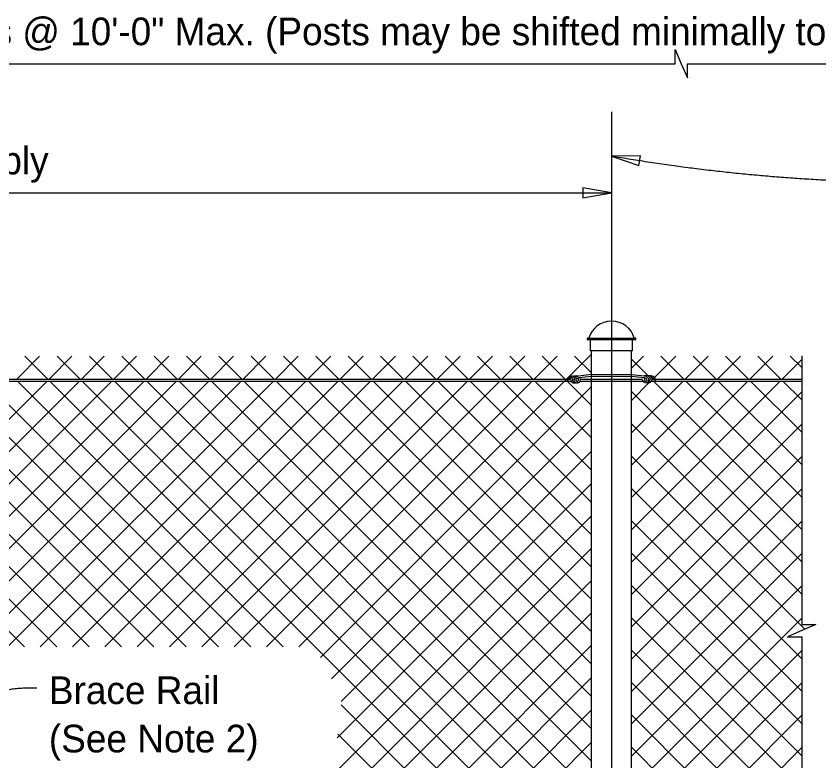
# Model space of a CAD drawing. Extents: x 0.2 to 40.8, y 0.5 to 25.7.
# Drawn here: x 10.28 to 16.13, y 20.28 to 25.7 of the extents above; entities that cross this region are included whole.
import ezdxf

# ---------------------------------------------------------------- set-up
doc = ezdxf.new("R2010")
doc.units = 0
for name, color, linetype in [('CL_Major', 7, 'Continuous'), ('Dimension', 7, 'Continuous'), ('Miscellaneous', 7, 'Continuous'), ('SteelMisc', 7, 'Continuous'), ('SteelMisc_h', 7, 'Continuous'), ('TextStructures', 7, 'Continuous')]:
    doc.layers.add(name, color=color, linetype=linetype)

msp = doc.modelspace()

# ---------------------------------------------------------------- linework, layer by layer
at = {"layer": 'CL_Major'}
msp.add_line((14.615, 25.0052), (14.615, 14.7584), dxfattribs=at)
at = {"layer": 'Dimension'}
for p, q in [((0.2352, 25.3556), (13.615, 25.3556)), ((4.615, 24.4146), (14.615, 24.4146))]:
    msp.add_line(p, q, dxfattribs=at)
for points in [[(13.615, 25.3556), (15.0787, 25.3556), (15.0787, 25.4589), (15.1237, 25.3556), (15.1687, 25.2523), (15.1687, 25.3556), (28.4596, 25.3556)], [(16.002, 23.2265), (16.002, 21.2702), (16.1053, 21.2702), (16.002, 21.2252), (15.8987, 21.1802), (16.002, 21.1802), (16.002, 20.2867)], [(16.002, 20.2867), (16.002, 19.2689), (16.1053, 19.2689), (16.002, 19.2239), (15.8987, 19.1789), (16.002, 19.1789), (16.002, 16.9746)]]:
    msp.add_lwpolyline(points, dxfattribs=at)
for points in [[(14.615, 24.6814), (14.815, 24.6135), (14.8262, 24.6832)], [(14.615, 24.4146), (14.4068, 24.4499), (14.4068, 24.3793)]]:
    msp.add_lwpolyline(points, close=True, dxfattribs=at)
for points in [[(18.5966, 24.4827), (17.7933, 24.4827), (16.4039, 24.4827), (15.2225, 24.5773), (14.615, 24.6814)], [(10.4281, 20.8052), (10.1586, 20.8133), (10.0405, 20.6549), (10.0376, 20.5337), (10.0422, 20.3659), (10.0503, 19.9529)]]:
    msp.add_open_spline(points, degree=2, dxfattribs=at)
at = {"layer": 'Miscellaneous'}
for p, q in [((12.336, 21.1064), (14.4692, 23.2396)), ((10.2805, 23.0578), (10.4472, 23.2245)), ((10.3397, 23.2245), (10.5064, 23.0578)), ((10.5162, 23.0578), (10.6829, 23.2245)), ((10.5754, 23.2245), (10.7421, 23.0578)), ((10.7519, 23.0578), (10.9186, 23.2245)), ((10.8111, 23.2245), (10.9778, 23.0578)), ((10.9876, 23.0578), (11.1543, 23.2245)), ((11.0468, 23.2245), (11.2135, 23.0578)), ((11.2233, 23.0578), (11.39, 23.2245)), ((11.2825, 23.2245), (11.4492, 23.0578)), ((11.459, 23.0578), (11.6257, 23.2245)), ((11.5182, 23.2245), (11.6849, 23.0578)), ((11.6947, 23.0578), (11.8614, 23.2245)), ((11.7539, 23.2245), (11.9206, 23.0578)), ((11.9304, 23.0578), (12.0971, 23.2245)), ((11.9896, 23.2245), (12.1563, 23.0578)), ((12.1661, 23.0578), (12.3328, 23.2245)), ((12.2253, 23.2245), (12.392, 23.0578)), ((12.4018, 23.0578), (12.5685, 23.2245)), ((12.461, 23.2245), (12.6277, 23.0578)), ((12.6375, 23.0578), (12.8042, 23.2245)), ((12.6967, 23.2245), (12.8634, 23.0578)), ((12.8732, 23.0578), (13.0399, 23.2245)), ((12.9324, 23.2245), (13.0991, 23.0578)), ((13.1089, 23.0578), (13.2756, 23.2245)), ((13.1681, 23.2245), (13.3348, 23.0578)), ((13.3446, 23.0578), (13.5113, 23.2245)), ((13.4038, 23.2245), (13.5705, 23.0578)), ((13.5803, 23.0578), (13.747, 23.2245)), ((13.6396, 23.2245), (13.8062, 23.0578)), ((13.816, 23.0578), (13.9827, 23.2245)), ((13.8753, 23.2245), (14.0419, 23.0578)), ((14.0517, 23.0578), (14.2184, 23.2245)), ((14.111, 23.2245), (14.2776, 23.0578)), ((14.2874, 23.0578), (14.4541, 23.2245)), ((14.3467, 23.2245), (14.4692, 23.1019)), ((14.7609, 23.1379), (14.8475, 23.2245)), ((14.7609, 23.2036), (14.8832, 23.0814)), ((14.928, 23.0694), (15.0832, 23.2245)), ((14.9757, 23.2245), (15.1424, 23.0578)), ((15.1522, 23.0578), (15.3189, 23.2245)), ((15.2114, 23.2245), (15.3781, 23.0578)), ((15.3879, 23.0578), (15.5546, 23.2245)), ((15.4471, 23.2245), (15.6138, 23.0578)), ((15.6236, 23.0578), (15.7903, 23.2245)), ((15.6828, 23.2245), (15.8495, 23.0578)), ((15.8593, 23.0578), (16.002, 23.2005)), ((15.9185, 23.2245), (16.002, 23.1411)), ((14.9165, 23.0578), (14.921, 23.0623)), ((8.3383, 20.88), (10.5014, 23.0431)), ((8.3998, 23.0431), (10.3365, 21.1064)), ((8.4925, 20.7985), (10.7372, 23.0431)), ((8.6355, 23.0431), (10.5722, 21.1064)), ((8.6467, 20.717), (10.9729, 23.0431)), ((8.8009, 20.6355), (11.2086, 23.0431)), ((8.8712, 23.0431), (10.8079, 21.1064)), ((8.9552, 20.554), (11.4443, 23.0431)), ((9.1069, 23.0431), (11.0436, 21.1064)), ((9.1094, 20.4725), (11.68, 23.0431)), ((9.2636, 20.391), (11.9157, 23.0431)), ((9.3426, 23.0431), (11.2793, 21.1064)), ((9.5783, 23.0431), (11.515, 21.1064)), ((9.814, 23.0431), (11.7507, 21.1064)), ((10.0497, 23.0431), (11.9864, 21.1064)), ((10.2043, 21.096), (12.1514, 23.0431)), ((10.2854, 23.0431), (12.2221, 21.1064)), ((10.4504, 21.1064), (12.3871, 23.0431)), ((10.5211, 23.0431), (14.4692, 19.095)), ((10.6861, 21.1064), (12.6228, 23.0431)), ((10.7568, 23.0431), (14.4692, 19.3307)), ((10.9218, 21.1064), (12.8585, 23.0431)), ((10.9925, 23.0431), (14.4692, 19.5664)), ((11.1575, 21.1064), (13.0942, 23.0431)), ((11.2282, 23.0431), (14.4692, 19.8021)), ((11.3932, 21.1064), (13.3299, 23.0431)), ((11.4639, 23.0431), (14.4692, 20.0378)), ((11.6289, 21.1064), (13.5656, 23.0431)), ((11.6996, 23.0431), (14.4692, 20.2735)), ((11.8646, 21.1064), (13.8013, 23.0431)), ((11.9353, 23.0431), (14.4692, 20.5092)), ((12.1003, 21.1064), (14.037, 23.0431)), ((12.1003, 21.1064), (14.037, 23.0431)), ((12.1711, 23.0431), (14.4692, 20.7449)), ((12.4068, 23.0431), (14.4692, 20.9806)), ((12.4951, 21.0298), (14.4692, 23.0039)), ((12.6425, 23.0431), (14.4692, 21.2163)), ((12.8782, 23.0431), (14.4692, 21.452)), ((13.1139, 23.0431), (14.4692, 21.6877)), ((13.3496, 23.0431), (14.4692, 21.9234)), ((13.5853, 23.0431), (14.4692, 22.1591)), ((13.821, 23.0431), (14.4692, 22.3948)), ((14.0567, 23.0431), (14.4692, 22.6305)), ((14.2924, 23.0431), (14.4692, 22.8662)), ((14.7609, 21.9594), (15.8446, 23.0431)), ((14.7609, 22.4308), (15.3732, 23.0431)), ((14.7609, 22.6665), (15.1375, 23.0431)), ((14.7609, 22.9022), (14.8904, 23.0317)), ((14.7653, 22.1995), (15.6089, 23.0431)), ((14.9214, 23.0431), (16.002, 21.9626)), ((15.1572, 23.0431), (16.002, 22.1983)), ((15.3929, 23.0431), (16.002, 22.434)), ((15.6286, 23.0431), (16.002, 22.6697)), ((15.8643, 23.0431), (16.002, 22.9054)), ((14.7609, 22.9679), (16.002, 21.7268)), ((14.7609, 21.7237), (16.002, 22.9648)), ((12.5756, 20.8746), (14.4692, 22.7682)), ((14.7609, 22.7322), (16.002, 21.4911)), ((14.7609, 21.488), (16.002, 22.7291)), ((12.6439, 20.7072), (14.4692, 22.5325)), ((14.7609, 22.4965), (16.023, 21.2344)), ((14.7609, 21.2523), (16.002, 22.4934)), ((12.6167, 20.4443), (14.4692, 22.2968)), ((14.7609, 22.2608), (16.002, 21.0197)), ((14.7609, 21.0166), (16.002, 22.2577)), ((11.5767, 19.1686), (14.4692, 22.0611)), ((14.7609, 22.0251), (16.002, 20.784)), ((14.7609, 20.7809), (16.002, 22.022)), ((11.7309, 19.0871), (14.4692, 21.8254)), ((14.7609, 21.7894), (16.002, 20.5483)), ((14.7609, 20.5452), (16.002, 21.7863)), ((11.8851, 19.0056), (14.4692, 21.5897)), ((14.7609, 21.5537), (16.002, 20.3126)), ((14.7609, 20.3095), (16.002, 21.5506)), ((12.0393, 18.9241), (14.4692, 21.354)), ((14.7609, 21.318), (16.002, 20.0769)), ((14.7609, 20.0738), (16.002, 21.3149)), ((12.1936, 18.8426), (14.4692, 21.1183)), ((14.7609, 21.0823), (16.002, 19.8412)), ((14.7609, 19.8381), (16.002, 21.0792)), ((12.3478, 18.7611), (14.4692, 20.8826)), ((14.7609, 20.8466), (16.002, 19.6055)), ((14.7609, 19.6024), (16.002, 20.8435)), ((12.6449, 20.6836), (14.4692, 18.8593)), ((12.502, 18.6796), (14.4692, 20.6469)), ((14.7609, 20.6109), (16.002, 19.3698)), ((14.7609, 19.3667), (16.002, 20.6078)), ((12.6214, 20.4714), (14.4692, 18.6236)), ((12.6562, 18.5982), (14.4692, 20.4112)), ((14.7609, 20.3752), (15.9395, 19.1966)), ((14.7609, 19.131), (16.002, 20.3721))]:
    msp.add_line(p, q, dxfattribs=at)
at = {"layer": 'SteelMisc'}
for p, q in [((14.4427, 23.3564), (14.7873, 23.3564)), ((14.7873, 23.3442), (14.4427, 23.3442)), ((14.461, 23.2645), (14.461, 23.3442)), ((14.7691, 23.2645), (14.7691, 23.3442)), ((14.7691, 23.2645), (14.461, 23.2645)), ((14.4692, 17.6192), (14.4692, 23.2644)), ((14.7609, 17.6192), (14.7609, 23.2644)), ((5.8052, 23.0578), (14.2941, 23.0578)), ((14.304, 23.0578), (14.3172, 23.0578)), ((14.4692, 23.0904), (14.3743, 23.0793)), ((14.4692, 23.0759), (14.3766, 23.0664)), ((14.387, 23.0578), (14.4692, 23.0578)), ((14.4692, 23.0904), (14.7604, 23.0921)), ((14.4692, 23.0759), (14.7604, 23.0776)), ((14.7604, 23.0921), (14.8547, 23.081)), ((14.7604, 23.0776), (14.8525, 23.0682)), ((14.7609, 23.0578), (14.8413, 23.0578)), ((14.9116, 23.0578), (14.9269, 23.0578)), ((14.9353, 23.0578), (16.002, 23.0578)), ((5.8052, 23.0431), (14.3207, 23.0431)), ((14.3856, 23.0431), (14.4692, 23.0431)), ((14.7609, 23.0431), (14.8439, 23.0431)), ((14.9067, 23.0431), (16.002, 23.0431))]:
    msp.add_line(p, q, dxfattribs=at)
for centre, start, end in [((14.4429, 23.3502), 91.1647, 268.8353), ((14.7872, 23.3502), 271.1647, 88.8353)]:
    msp.add_arc(centre, 0.00613, start, end, dxfattribs=at)
for centre, major_axis, ratio, start_param, end_param in [((14.6157, 23.3154), (0.1711, 0), 0.957868, 0.252602, 2.888574), ((14.3283, 23.0436), (0.0373, 0), 0.957868, 1.486836, 3.108042), ((14.3494, 23.0039), (-0.0724, 0), 0.957868, 5.162149, 5.652106), ((14.3419, 23.0555), (-0.0249, 0), 0.957868, 6.009018, 7.089857), ((14.3408, 23.058), (0.023, 0), 0.957868, 1.29026, 2.970541), ((14.3595, 23.0527), (0.0295, 0), 0.957868, 1.220941, 4.039556), ((14.373, 23.0544), (-0.0303, -0.0108), 0.724765, 4.35367, 6.324556), ((14.3697, 23.0504), (-0.0139, 0), 0.957868, 5.22362, 6.905413), ((14.3781, 23.0415), (-0.0259, 0), 0.957868, 4.777514, 5.62749), ((14.3624, 23.0538), (0.0119, 0), 0.957868, 5.725876, 7.416677), ((14.3626, 23.0525), (0.0251, 0), 0.957868, 0.407687, 0.609214), ((14.8661, 23.0543), (-0.0251, 0), 0.957868, 5.673972, 5.875498), ((14.8556, 23.0562), (0.0303, -0.0108), 0.724765, 6.241815, 8.212701), ((14.8506, 23.0433), (0.0259, 0), 0.957868, 0.655696, 1.505671), ((14.8663, 23.0556), (-0.0119, 0), 0.957868, 5.149694, 6.840495), ((14.8691, 23.0544), (-0.0295, 0), 0.957868, 2.243629, 5.062245), ((14.859, 23.0521), (0.0139, 0), 0.957868, 5.660958, 7.342751), ((14.8879, 23.0598), (-0.023, 0), 0.957868, 3.312645, 4.992926), ((14.9004, 23.0453), (-0.0373, 0), 0.957868, 3.175144, 4.79635), ((14.8867, 23.0573), (0.0249, 0), 0.957868, 5.476514, 6.557353), ((14.8792, 23.0056), (0.0724, 0), 0.957868, 0.631079, 1.121037), ((14.3433, 23.0515), (0.0231, 0), 0.957868, 3.779554, 4.879821), ((14.3494, 23.0458), (0.0206, -0.0021), 0.798607, 4.32653, 5.220153), ((14.3629, 23.0458), (0.0206, -0.0021), 0.798607, 3.333154, 5.220153), ((14.364, 23.048), (-0.00795, 0), 0.957868, 6.140374, 9.314262), ((14.3555, 23.0646), (0.0391, 0), 0.957868, 5.082588, 5.41974), ((14.3624, 23.0538), (0.0119, 0), 0.957868, 5.639684, 5.723117), ((14.3626, 23.0525), (0.0251, 0), 0.957868, 5.531357, 6.227833), ((14.8661, 23.0543), (-0.0251, 0), 0.957868, 0.055352, 0.751829), ((14.8732, 23.0664), (-0.0391, 0), 0.957868, 0.863445, 1.200597), ((14.8663, 23.0556), (-0.0119, 0), 0.957868, 0.560069, 0.643501), ((14.8646, 23.0498), (0.00795, 0), 0.957868, 3.252108, 6.425997), ((14.8658, 23.0476), (-0.0206, -0.0021), 0.798607, 1.063032, 2.950031), ((14.8792, 23.0476), (-0.0206, -0.0021), 0.798607, 1.063032, 1.956656), ((14.8853, 23.0533), (-0.0231, 0), 0.957868, 1.403365, 2.503632)]:
    msp.add_ellipse(centre, major_axis=major_axis, ratio=ratio, start_param=start_param, end_param=end_param, dxfattribs=at)
at = {"layer": 'SteelMisc_h'}
for p, q in [((14.4692, 23.0578), (14.7609, 23.0578)), ((14.4692, 23.0431), (14.7609, 23.0431))]:
    msp.add_line(p, q, dxfattribs=at)

# ---------------------------------------------------------------- texts
at = {"layer": 'TextStructures'}
for s, p in [('Equal Spaces @ 10\'-0" Max. (Posts may be shifted minimally to meet required clearances)', (8.5826, 25.4902)), ('End Post Assembly', (8.1753, 24.5492)), ('Brace Rail', (10.5146, 20.6895)), ('(See Note 2)', (10.5146, 20.3375))]:
    msp.add_text(s, height=0.2016, dxfattribs=at).set_placement(p)

doc.saveas('drawing.dxf')
